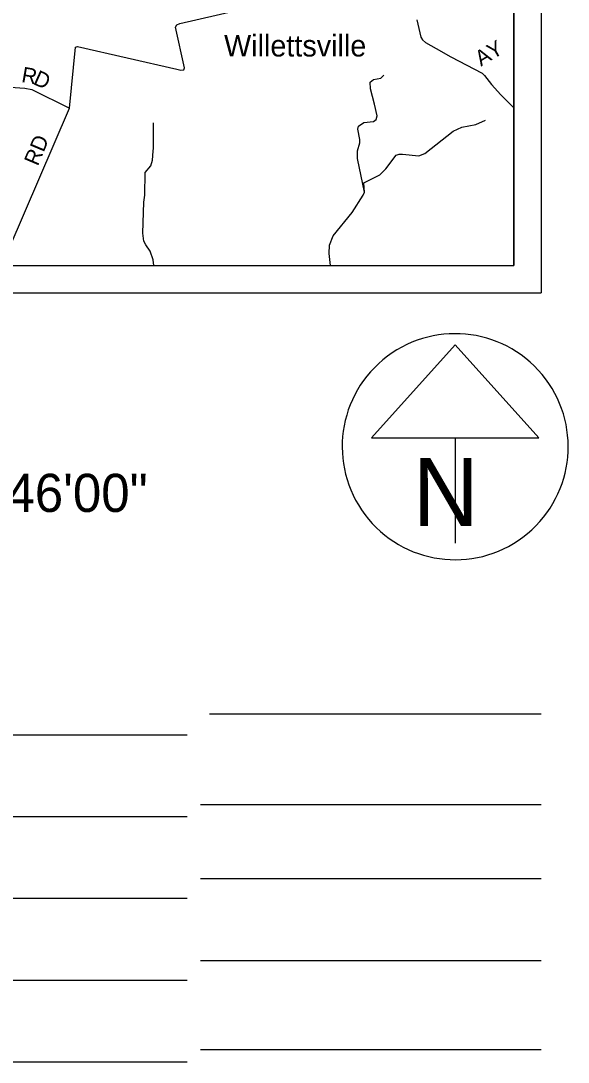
# Model space of a CAD drawing. Extents: x 0 to 48.6, y 0 to 22.
# Drawn here: x 7.09 to 9.099, y 11.177 to 14.998 of the extents above; entities that cross this region are included whole.
import ezdxf

# ---------------------------------------------------------------- set-up
doc = ezdxf.new("R2010")
doc.units = 0
for name, color, linetype in [('GM_X_Corporation', 7, 'Continuous'), ('GM_X_Minor_River', 7, 'Continuous'), ('GM_X_State_Route', 7, 'Continuous'), ('GM_X_Township_Road', 7, 'Continuous'), ('GM_X_Township_Road_Text', 7, 'Continuous'), ('GM_X_Unincorporated_Text', 7, 'Continuous'), ('SH_Data', 7, 'Continuous'), ('SH_Text', 7, 'Continuous')]:
    doc.layers.add(name, color=color, linetype=linetype)

msp = doc.modelspace()

# ---------------------------------------------------------------- linework, layer by layer
at = {"layer": 'GM_X_Corporation'}
msp.add_lwpolyline([(5.0944, 14.1), (8.9, 14.1), (8.9, 19.5692), (8.5348, 19.2897), (7.2261, 18.2847), (6.9471, 18.0777), (6.5365, 17.7727), (5.8387, 17.2541), (5.5264, 17.0064), (4.6225, 16.3345), (4.044, 15.9033), (4.0346, 15.8959), (4.0398, 15.887), (4.3544, 15.3539), (4.4679, 15.1616), (4.7542, 14.6766)], close=True, dxfattribs=at)
at = {"layer": 'GM_X_Minor_River'}
for points in [[(8.2265, 14.1), (8.2218, 14.1444), (8.2225, 14.1748), (8.2362, 14.2087), (8.3069, 14.2954), (8.3471, 14.3586), (8.351, 14.3692), (8.3254, 14.4931), (8.3261, 14.5212), (8.3345, 14.5507), (8.3346, 14.5628), (8.3268, 14.6005), (8.3292, 14.6118), (8.349, 14.6248), (8.3843, 14.6285), (8.3946, 14.6364), (8.3982, 14.65), (8.3877, 14.6918), (8.3733, 14.7485), (8.3718, 14.7736), (8.3847, 14.7833), (8.4113, 14.7882), (8.4228, 14.7987)], [(7.5782, 14.1), (7.5757, 14.1214), (7.5651, 14.153), (7.5484, 14.1764), (7.5418, 14.1901), (7.5372, 14.219), (7.5417, 14.3331), (7.5451, 14.3589), (7.5465, 14.4415), (7.5673, 14.4659), (7.5728, 14.4863), (7.5763, 14.5193), (7.5768, 14.5306), (7.5769, 14.6239)], [(8.351, 14.3692), (8.3492, 14.4033), (8.4082, 14.4325), (8.4293, 14.455), (8.4682, 14.5053), (8.4788, 14.5094), (8.4913, 14.5092), (8.5506, 14.5031), (8.5734, 14.5108), (8.6766, 14.5933), (8.7093, 14.608), (8.7601, 14.6172), (8.7955, 14.6338)]]:
    msp.add_lwpolyline(points, dxfattribs=at)
at = {"layer": 'GM_X_State_Route'}
msp.add_lwpolyline([(8.5439, 15.0024), (8.559, 14.9377), (8.5642, 14.9281), (8.5752, 14.9189), (8.6149, 14.897), (8.6686, 14.8658), (8.783, 14.806), (8.7923, 14.7971), (8.8179, 14.765), (8.852, 14.7266), (8.8988, 14.6804), (8.9, 14.6794)], dxfattribs=at)
at = {"layer": 'GM_X_Township_Road'}
for points in [[(7.0398, 14.1), (7.0477, 14.1622), (7.268, 14.6779), (7.2906, 14.9021), (7.2983, 14.9038), (7.6625, 14.8205), (7.6772, 14.8167), (7.6879, 14.8187), (7.6911, 14.8254), (7.6578, 14.9749), (7.6622, 14.9831), (7.6738, 14.9885), (8.1804, 15.1061)], [(6.5079, 14.7806), (6.9133, 14.7616), (7.0509, 14.7543), (7.104, 14.7505), (7.1301, 14.746), (7.268, 14.6779)]]:
    msp.add_lwpolyline(points, dxfattribs=at)
at = {"layer": 'SH_Data'}
for p, q in [((9, 21), (9, 14)), ((8.9, 20.9), (8.9, 14.1)), ((2.1, 14.1), (8.9, 14.1)), ((2, 14), (9, 14)), ((8.6845, 13.8091), (8.3769, 13.4678)), ((8.9921, 13.4678), (8.6845, 13.8091)), ((8.3769, 13.4678), (8.9921, 13.4678)), ((8.6845, 13.4678), (8.6845, 13.0811)), ((8.6845, 13.4353), (8.6845, 13.4353)), ((8.6845, 13.4353), (8.6845, 13.4353)), ((7.7827, 12.4553), (9, 12.4553)), ((7.7, 12.3767), (4.4937, 12.3767)), ((9, 12.1207), (7.75, 12.1207)), ((7.7, 12.0767), (3.9895, 12.0767)), ((9, 11.8491), (7.75, 11.8491)), ((7.7, 11.7767), (3.6192, 11.7767)), ((9, 11.5491), (7.75, 11.5491)), ((7.7, 11.4767), (3.3288, 11.4767)), ((9, 11.2223), (7.75, 11.2223)), ((7.7, 11.1767), (4.7452, 11.1767))]:
    msp.add_line(p, q, dxfattribs=at)
msp.add_arc((8.6845, 13.4353), 0.4148, 129.7798, 129.7633, dxfattribs=at)

# ---------------------------------------------------------------- texts
at = {"layer": 'GM_X_Township_Road_Text'}
for s, height, rotation, p in [('Y', 0.0568, 29.4114, (8.8215, 14.8556)), ('A', 0.0568, 31.4557, (8.7793, 14.8298)), ('R', 0.0568, 350.068, (7.0898, 14.774)), ('D', 0.0568, 335.9617, (7.1322, 14.7671)), ('RD', 0.05682, 67.1899, (7.1521, 14.4627))]:
    msp.add_text(s, height=height, rotation=rotation, dxfattribs=at).set_placement(p)
at = {"layer": 'GM_X_Unincorporated_Text'}
msp.add_text('Willettsville', height=0.078977, rotation=0, dxfattribs=at).set_placement((7.836, 14.8673))
at = {"layer": 'SH_Data'}
msp.add_text('N', height=0.25, dxfattribs=at).set_placement((8.5292, 13.144))
at = {"layer": 'SH_Text'}
msp.add_text('LATITUDE:  N39°17\'28"     LONGITUDE:  W83°46\'00"', height=0.14, dxfattribs=at).set_placement((3.071, 13.1959))

doc.saveas('drawing.dxf')
